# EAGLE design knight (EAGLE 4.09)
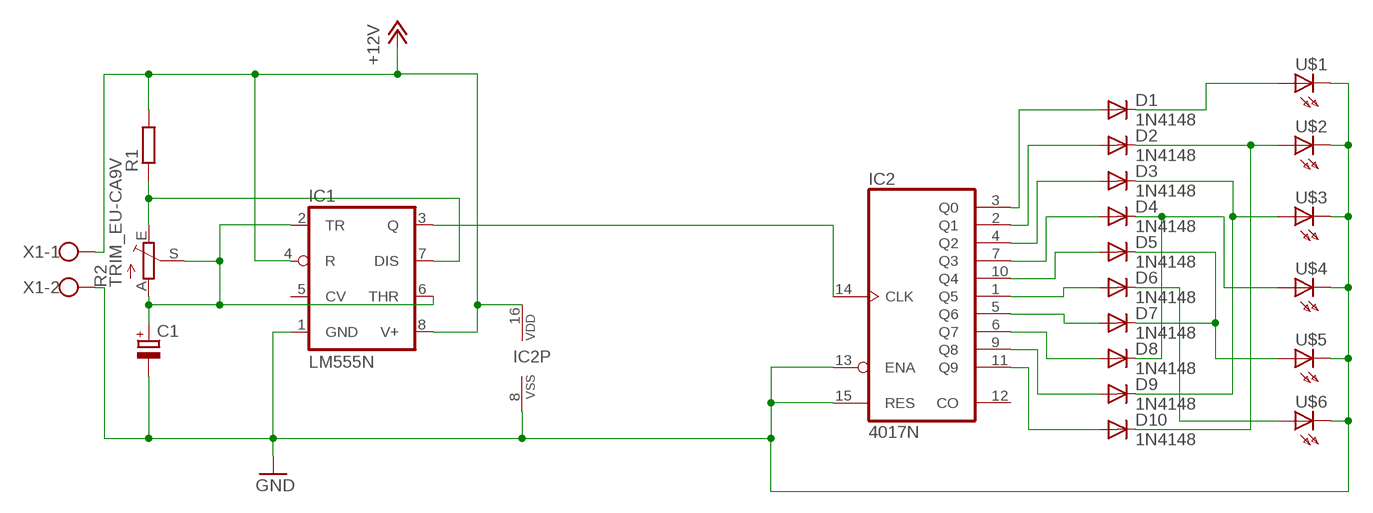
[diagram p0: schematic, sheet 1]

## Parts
C1  CPOL-EUE5-8.5  [E5-8,5]
D1  1N4148  [DO35-10]
D2  1N4148  [DO35-10]
D3  1N4148  [DO35-10]
D4  1N4148  [DO35-10]
D5  1N4148  [DO35-10]
D6  1N4148  [DO35-10]
D7  1N4148  [DO35-10]
D8  1N4148  [DO35-10]
D9  1N4148  [DO35-10]
D10  1N4148  [DO35-10]
IC1  LM555N  [DIL08]
IC2  4017N  [DIL16]
R1  R-EU_0207/10  [0207/10]
R2  TRIM_EU-CA9V  [CA9V]
U$1  LED5MM  [LED5MM]
U$2  LED5MM  [LED5MM]
U$3  LED5MM  [LED5MM]
U$4  LED5MM  [LED5MM]
U$5  LED5MM  [LED5MM]
U$6  LED5MM  [LED5MM]
X1  W237-02P  [W237-132]

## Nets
GND: C1.- IC1.1(GND) IC2.8(VSS) IC2.13(ENA) IC2.15(RES) U$1.K(C) U$2.K(C) U$3.K(C) U$4.K(C) U$5.K(C) U$6.K(C) X1.2
N$1: IC1.4(R) IC1.8(V+) IC2.16(VDD) R1.2 X1.1 ; supply symbol labelled +12V
N$2: C1.+ IC1.2(TR) IC1.6(THR) R2.A R2.S
N$3: IC1.7(DIS) R1.1 R2.E
N$8: IC1.3(Q) IC2.14(CLK)
N$11: D1.A IC2.3(Q0)
N$12: D2.A IC2.2(Q1)
N$13: D3.A IC2.4(Q2)
N$14: D4.A IC2.7(Q3)
N$15: D5.A IC2.10(Q4)
N$16: D6.A IC2.1(Q5)
N$17: D10.A IC2.11(Q9)
N$18: D9.A IC2.9(Q8)
N$19: D8.A IC2.6(Q7)
N$20: D7.A IC2.5(Q6)
N$21: D1.C U$1.A
N$22: D2.C D10.C U$2.A
N$24: D3.C D9.C U$3.A
N$26: D4.C D8.C U$4.A
N$27: D5.C D7.C U$5.A
N$28: D6.C U$6.A
Unconnected: IC1.5(CV) IC2.12(CO)

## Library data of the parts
C1 = rcl:CPOL-EU: POLARIZED CAPACITOR, European symbol
D1-D10 = diode:1N4148: DIODE
IC1 = linear:*555: TIMER
IC2 = 40xx:4017: COUNTER/DIVIDER
R1 = rcl:R-EU_: RESISTOR, European symbol
R2 = pot:TRIM_EU-: POTENTIOMETER
U$1-U$6 = led:LED: LED
X1 = con-wago-508:W237-02P: WAGO SREW CLAMP

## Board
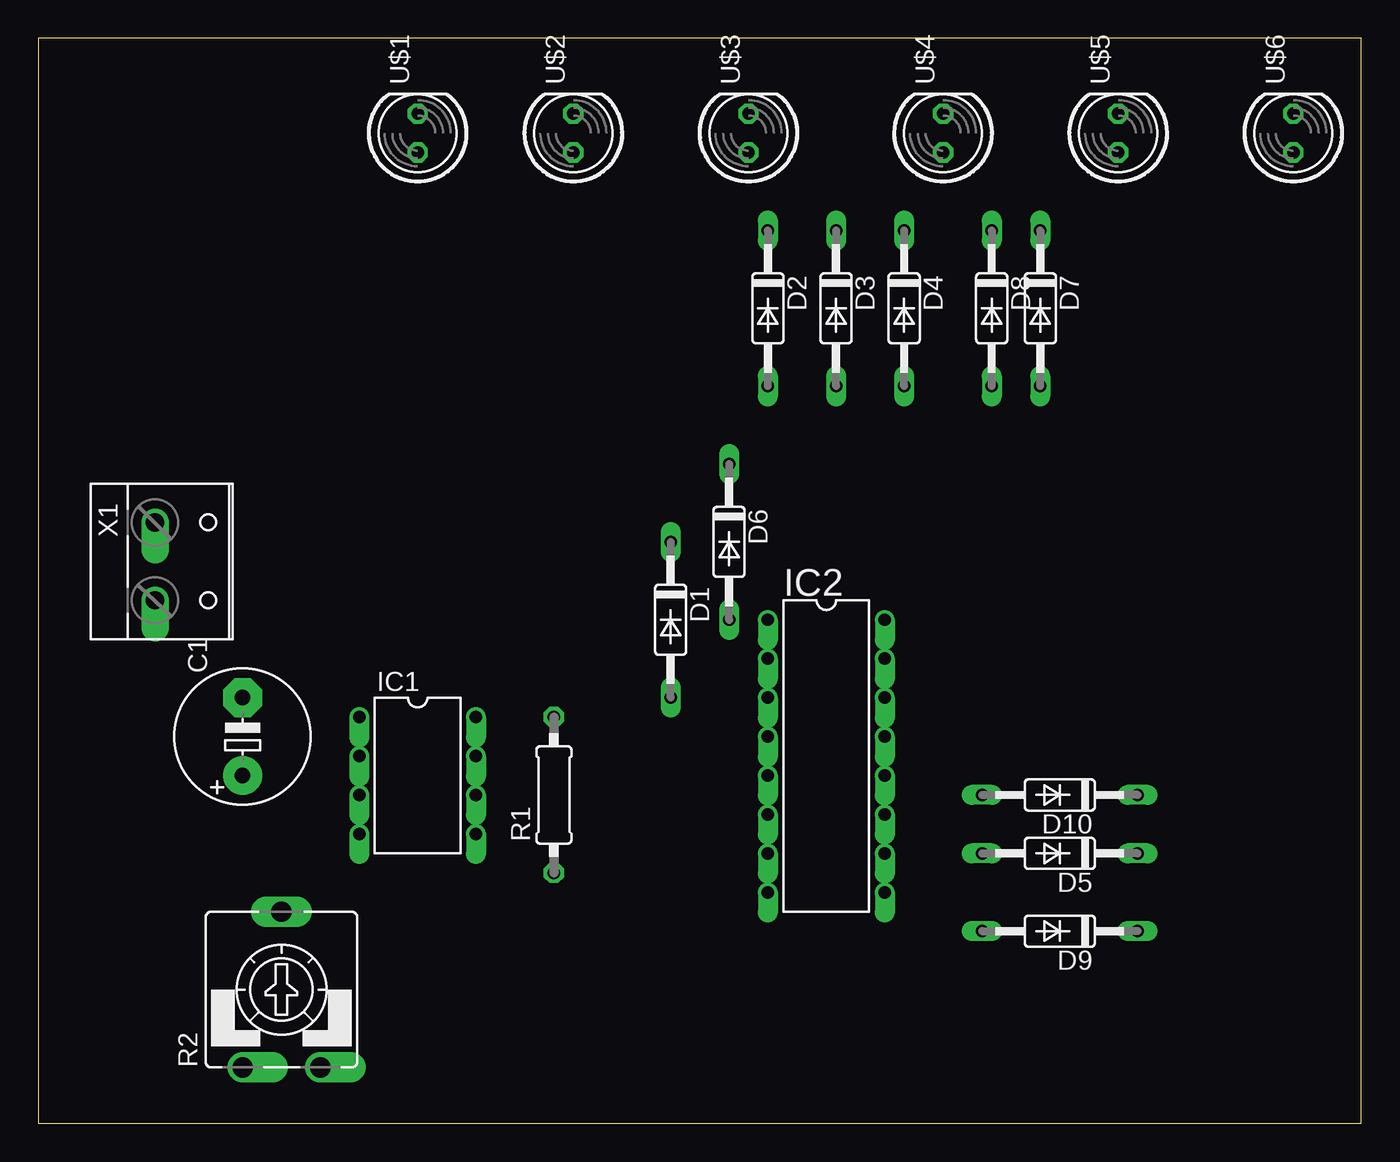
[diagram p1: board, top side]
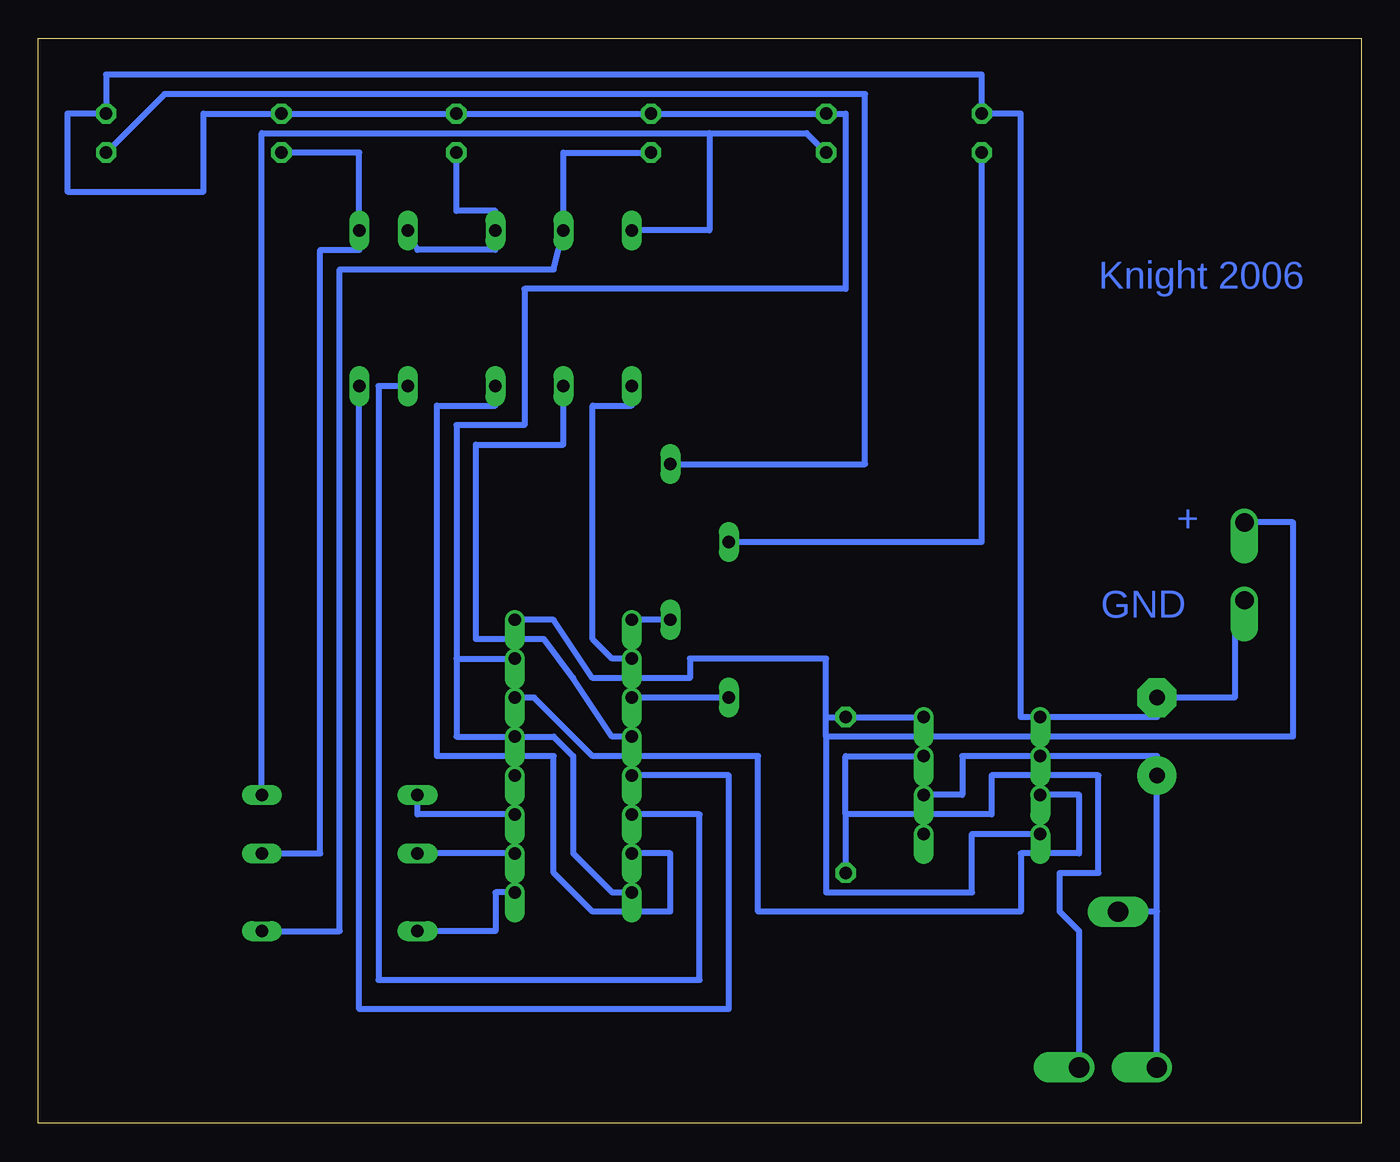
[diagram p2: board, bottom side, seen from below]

Size 86.34 x 70.79 mm. Coordinates in mm from the lower left corner, seen from the top.
Outline: 0,0 86.34,0 86.34,70.79 0,70.79 0,0
Copper layers used: Bottom

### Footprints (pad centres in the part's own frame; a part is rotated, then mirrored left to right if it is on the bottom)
E5-8,5 = drill 1.016 pad 2.54 round: + -2.54,0 | drill 1.016 pad 2.54 octagon: - 2.54,0
DO35-10 = drill 0.813 long: A 5.08,0; C -5.08,0
DIL08 = drill 0.813 offset: 1 -3.81,-3.81; 2 -1.27,-3.81; 3 1.27,-3.81; 4 3.81,-3.81; 5 3.81,3.81; 6 1.27,3.81; 7 -1.27,3.81; 8 -3.81,3.81
DIL16 = drill 0.813 offset: 1 -8.89,-3.81; 2 -6.35,-3.81; 3 -3.81,-3.81; 4 -1.27,-3.81; 5 1.27,-3.81; 6 3.81,-3.81; 7 6.35,-3.81; 8 8.89,-3.81; 9 8.89,3.81; 10 6.35,3.81; 11 3.81,3.81; 12 1.27,3.81; 13 -1.27,3.81; 14 -3.81,3.81; 15 -6.35,3.81; 16 -8.89,3.81
0207/10 = drill 0.813 octagon: 1 -5.08,0; 2 5.08,0
CA9V = drill 1.321 offset: A -2.54,-5.08; E 2.54,-5.08 | drill 1.321 long: S 0,5.08
LED5MM = drill 0.813 octagon: A -1.27,0; K 1.27,0
W237-132 = drill 1.194 offset: 1 -2.54,-0.635; 2 2.54,-0.635

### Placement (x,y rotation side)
C1  13.33,25.23 90 top
D1  41.27,32.86 270 top
D2  47.62,53.18 270 top
D3  52.07,53.18 270 top
D4  56.51,53.18 270 top
D5  66.67,17.62 180 top
D6  45.08,37.94 270 top
D7  65.4,53.18 270 top
D8  62.23,53.18 270 top
D9  66.67,12.54 180 top
D10  66.67,21.43 180 top
IC1  24.76,22.7 270 top
IC2  51.43,23.96 270 top
R1  33.65,21.43 90 top
R2  15.87,8.73 0 top
U$1  24.76,64.6 90 top
U$2  34.92,64.6 90 top
U$3  46.35,64.6 90 top
U$4  59.05,64.6 90 top
U$5  70.48,64.6 90 top
U$6  81.91,64.6 90 top
X1  8.25,36.66 270 top

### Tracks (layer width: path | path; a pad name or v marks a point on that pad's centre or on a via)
GND
  Bottom 0.381: X1.2 8.25,34.12 8.25,27.78 C1.- 13.33,26.51 IC1.1 22.22,26.51 22.22,65.88 U$1.K 24.76,68.41 81.91,68.41 U$6.K 84.45,65.88 84.45,60.8 75.56,60.8 75.56,65.88 U$5.K U$4.K U$3.K U$2.K 33.65,65.88 33.65,54.45 54.61,54.45 54.61,45.55 59.05,45.55 59.05,30.32 | IC2.8 48.89,15.08 51.43,17.62 51.43,23.96 52.7,25.23 IC2.13 59.05,25.23 59.05,30.32 | 59.05,30.32 IC2.15
N$1
  Bottom 0.381: 34.92,25.23 34.92,26.51 | 34.92,25.23 34.92,15.08 25.39,15.08 25.39,18.89 IC1.4 | 34.92,26.51 R1.2 IC1.8 | 34.92,26.51 34.92,30.32 43.81,30.32 43.81,29.05 50.16,29.05 52.7,32.86 IC2.16 | 34.92,25.23 4.44,25.23 4.44,39.2 X1.1
N$2
  Bottom 0.381: R2.A 13.33,13.81 | 13.33,13.81 R2.S | IC1.6 26.03,21.43 26.03,23.96 IC1.2 13.33,23.96 C1.+ 13.33,13.81
N$3
  Bottom 0.381: 33.65,20.16 33.65,23.96 IC1.7 | 33.65,20.16 R1.1 | 33.65,20.16 24.12,20.16 24.12,22.7 17.14,22.7 17.14,16.35 19.68,16.35 19.68,13.81 18.41,12.54 R2.E
N$8
  Bottom 0.381: IC1.3 18.41,21.43 18.41,17.62 22.22,17.62 22.22,13.81 39.37,13.81 39.37,23.96 50.16,23.96 53.97,27.78 IC2.14
N$11
  Bottom 0.381: D1.A IC2.3
N$12
  Bottom 0.381: IC2.2 48.89,30.32 50.16,31.59 50.16,46.83 47.62,46.83 D2.A
N$13
  Bottom 0.381: IC2.4 48.89,25.23 51.43,29.05 53.34,31.59 57.78,31.59 57.78,44.29 52.07,44.29 D3.A
N$14
  Bottom 0.381: IC2.7 45.08,17.62 45.08,13.81 50.16,13.81 52.7,16.35 52.7,23.96 60.32,23.96 60.32,46.83 56.51,46.83 D4.A
N$15
  Bottom 0.381: IC2.10 D5.A
N$16
  Bottom 0.381: D6.A IC2.1
N$17
  Bottom 0.381: IC2.11 61.59,20.16 D10.A
N$18
  Bottom 0.381: IC2.9 56.51,15.08 56.51,12.54 D9.A
N$19
  Bottom 0.406: D8.A 64.13,48.09 64.13,9.36 43.18,9.36 43.18,20.16 IC2.6
N$20
  Bottom 0.381: IC2.5 41.27,22.7 41.27,7.46 65.4,7.46 D7.A
N$21
  Bottom 0.381: U$1.A 24.76,37.94 D1.C
N$22
  Bottom 0.381: D10.C 71.75,64.6 42.54,64.6 | 42.54,64.6 36.19,64.6 U$2.A | 42.54,64.6 42.54,58.26 D2.C
N$24
  Bottom 0.381: D9.C 66.67,12.54 66.67,55.72 52.7,55.72 D3.C 52.07,63.34 U$3.A
N$26
  Bottom 0.381: D8.C 61.59,56.98 56.51,56.98 D4.C 56.51,59.52 59.05,59.52 U$4.A
N$27
  Bottom 0.381: D5.C 67.94,17.62 67.94,56.98 65.4,56.98 D7.C 65.4,63.34 U$5.A
N$28
  Bottom 0.381: D6.C 32.38,43.02 32.38,67.14 78.1,67.14 U$6.A

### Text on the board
Bottom: Knight 2006 | + | GND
